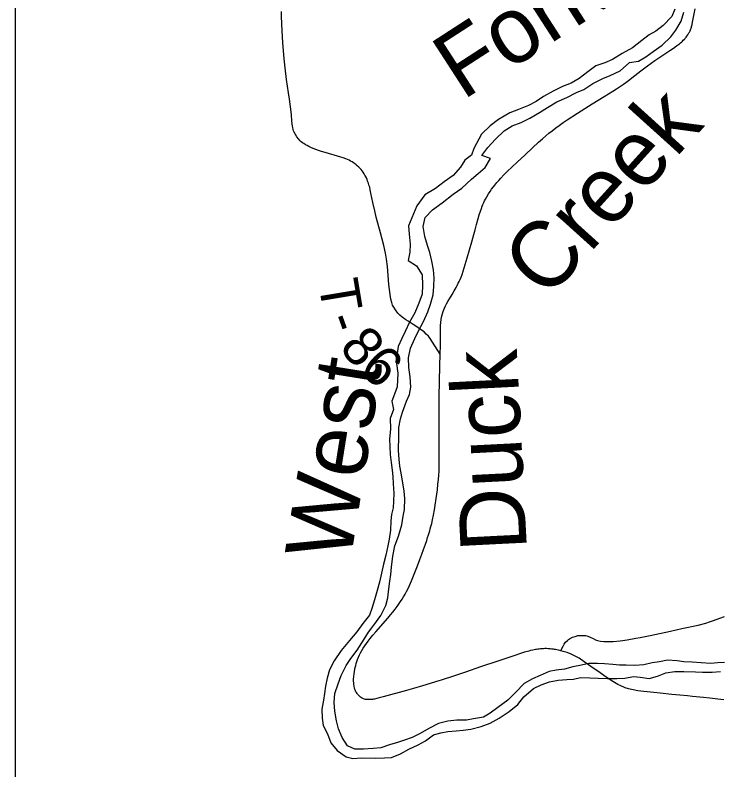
# Model space of a CAD drawing. Extents: x 0 to 34, y 0 to 22.
# Drawn here: x 2.1 to 3.105, y 14.853 to 15.933 of the extents above; entities that cross this region are included whole.
import ezdxf

# ---------------------------------------------------------------- set-up
doc = ezdxf.new("R2010")
doc.units = 0
for name, color, linetype in [('GM_X_Corporation', 7, 'Continuous'), ('GM_X_Major_River', 7, 'Continuous'), ('GM_X_Major_River_Text', 7, 'Continuous'), ('GM_X_State_Route', 7, 'Continuous'), ('GM_X_Township_Road', 7, 'Continuous'), ('GM_X_Township_Road_Text', 7, 'Continuous'), ('SH_Data', 7, 'Continuous'), ('SH_Text', 7, 'Continuous')]:
    doc.layers.add(name, color=color, linetype=linetype)

msp = doc.modelspace()

# ---------------------------------------------------------------- linework, layer by layer
at = {"layer": 'GM_X_Corporation'}
msp.add_lwpolyline([(2.1, 19.4241), (2.1, 14.1), (8.9, 14.1), (8.9, 16.8499)], dxfattribs=at)
at = {"layer": 'GM_X_Major_River'}
for points in [[(3.0436, 15.9414), (3.0392, 15.9311), (3.0268, 15.918), (3.0167, 15.9099), (3.0069, 15.9049), (2.9964, 15.8967), (2.9833, 15.8863), (2.9686, 15.8782), (2.9547, 15.8693), (2.9434, 15.8645), (2.9309, 15.8606), (2.9193, 15.8517), (2.9069, 15.8424), (2.8956, 15.8354), (2.8828, 15.8307), (2.8696, 15.8241), (2.8557, 15.8163), (2.8452, 15.8093), (2.8346, 15.8035), (2.8203, 15.798), (2.8075, 15.7933), (2.7913, 15.7836), (2.7797, 15.7747), (2.7673, 15.7628), (2.7562, 15.7421), (2.7529, 15.7326)], [(2.7677, 15.7321), (2.7763, 15.7435), (2.7871, 15.7555), (2.7995, 15.7674), (2.8111, 15.7747), (2.824, 15.7795), (2.8364, 15.7853), (2.8499, 15.7935), (2.8616, 15.8008), (2.8751, 15.809), (2.8891, 15.8153), (2.903, 15.8223), (2.9136, 15.8266), (2.9263, 15.8351), (2.9407, 15.8421), (2.9512, 15.8464), (2.9655, 15.8531), (2.979, 15.865), (2.9919, 15.8671), (3.0024, 15.8733), (3.0129, 15.881), (3.0257, 15.8899), (3.038, 15.9019), (3.0451, 15.9114), (3.0529, 15.9244), (3.0565, 15.937)], [(2.7529, 15.7326), (2.7432, 15.7253), (2.7369, 15.7153), (2.7264, 15.7034), (2.714, 15.6945), (2.7013, 15.6849), (2.6862, 15.6759), (2.6747, 15.6602), (2.6626, 15.6316), (2.6635, 15.6195), (2.6652, 15.6055), (2.6646, 15.5937), (2.6621, 15.5819), (2.6743, 15.5745), (2.6821, 15.5613), (2.683, 15.5469), (2.6825, 15.5336), (2.6773, 15.5207), (2.6718, 15.5073), (2.6641, 15.4936), (2.6582, 15.4802), (2.653, 15.4703), (2.6482, 15.4588), (2.6461, 15.4455), (2.6455, 15.4345), (2.6476, 15.4209), (2.6464, 15.4011), (2.6427, 15.3908), (2.6387, 15.3809), (2.6415, 15.3688), (2.6367, 15.3562), (2.6369, 15.3411), (2.6356, 15.3266), (2.6361, 15.316), (2.6363, 15.3043), (2.638, 15.2929), (2.6396, 15.2823), (2.6405, 15.2728), (2.641, 15.2626), (2.6416, 15.2493), (2.6414, 15.2379), (2.6407, 15.2284), (2.6382, 15.2189), (2.6376, 15.2094), (2.637, 15.1961), (2.6349, 15.1836), (2.6331, 15.1741), (2.6303, 15.1604), (2.627, 15.1475), (2.6242, 15.1349), (2.6213, 15.122), (2.6177, 15.1098), (2.6141, 15.0968), (2.6104, 15.0843), (2.6068, 15.0747), (2.5975, 15.0628), (2.5889, 15.051), (2.5785, 15.0383), (2.5665, 15.0241), (2.5565, 15.0095), (2.5498, 14.9966), (2.5462, 14.9844), (2.5441, 14.9733), (2.5427, 14.9627), (2.5413, 14.9532), (2.5388, 14.9403), (2.5394, 14.9274), (2.5407, 14.9171), (2.5469, 14.9051), (2.5516, 14.8922), (2.5605, 14.881), (2.5735, 14.8721), (2.583, 14.8699), (2.5948, 14.8708), (2.616, 14.8704), (2.6285, 14.8705), (2.6384, 14.871), (2.6515, 14.8765), (2.6632, 14.8831), (2.6764, 14.8894), (2.6869, 14.8952), (2.6986, 14.9037), (2.7091, 14.9065), (2.719, 14.9082), (2.7307, 14.9091), (2.7409, 14.9104), (2.7519, 14.9116), (2.7666, 14.9156), (2.7795, 14.9204), (2.7923, 14.9274), (2.8069, 14.9371), (2.8193, 14.9471), (2.8279, 14.9578), (2.8414, 14.9698), (2.8523, 14.9752), (2.8644, 14.9792), (2.8768, 14.9816), (2.889, 14.9829), (2.8988, 14.9834), (2.909, 14.9855), (2.9219, 14.9853)], [(2.9429, 15.0053), (2.933, 15.0055), (2.9205, 15.0054), (2.9103, 15.0033), (2.8978, 15.0009), (2.8861, 14.9977), (2.874, 14.996), (2.8638, 14.994), (2.8513, 14.9885), (2.84, 14.9838), (2.8284, 14.9768), (2.8157, 14.9641), (2.8048, 14.9533), (2.7905, 14.9425), (2.7797, 14.9344), (2.7699, 14.9286), (2.7559, 14.9265), (2.7457, 14.9245), (2.732, 14.9247), (2.7188, 14.923), (2.7056, 14.9197), (2.692, 14.9127), (2.6796, 14.9057), (2.6679, 14.8999), (2.657, 14.8959), (2.6468, 14.8928), (2.6358, 14.8892), (2.623, 14.8852), (2.612, 14.884), (2.5984, 14.883), (2.5859, 14.8832), (2.5756, 14.888), (2.5678, 14.8997), (2.5627, 14.9121), (2.5599, 14.9235), (2.5575, 14.9375), (2.5562, 14.9496), (2.5575, 14.9625), (2.5619, 14.9766), (2.5662, 14.9884), (2.5736, 15.0026), (2.5803, 15.0125), (2.5893, 15.0248), (2.5993, 15.0405), (2.6056, 15.0504), (2.613, 15.0604), (2.6231, 15.0742), (2.6305, 15.0887), (2.633, 15.0997), (2.6347, 15.1123), (2.6361, 15.1233), (2.6375, 15.1328), (2.6385, 15.1434), (2.6405, 15.159), (2.6434, 15.1739), (2.6485, 15.1876), (2.6532, 15.204), (2.6553, 15.2161), (2.6571, 15.226), (2.6576, 15.2416), (2.6567, 15.2522), (2.6547, 15.2639), (2.6522, 15.2779), (2.6505, 15.2878), (2.6493, 15.298), (2.6483, 15.3101), (2.6488, 15.3306), (2.649, 15.3431), (2.6511, 15.3553), (2.654, 15.3648), (2.6599, 15.3808), (2.6643, 15.3904), (2.6661, 15.401), (2.6651, 15.4158), (2.663, 15.4287), (2.6628, 15.4427), (2.6657, 15.4564), (2.672, 15.4705), (2.6764, 15.4804), (2.6841, 15.4946), (2.6904, 15.5087), (2.6944, 15.5194), (2.698, 15.5327), (2.699, 15.5449), (2.6996, 15.5574), (2.6983, 15.5688), (2.6962, 15.5809), (2.6934, 15.5933), (2.6899, 15.6035), (2.6859, 15.6164), (2.6838, 15.6308), (2.6867, 15.6433), (2.6971, 15.6545), (2.711, 15.6645), (2.7264, 15.6769), (2.7392, 15.6854), (2.7527, 15.6981), (2.7624, 15.7062), (2.7725, 15.715), (2.7799, 15.7277), (2.7677, 15.7321)], [(3.115, 15.0072), (3.1047, 15.0063), (3.0953, 15.0058), (3.0812, 15.0064), (3.0687, 15.0077), (3.0566, 15.008), (3.0471, 15.0094), (3.0334, 15.0103), (3.0217, 15.0082), (3.0115, 15.0066), (2.9994, 15.0038), (2.9865, 15.0025), (2.974, 15.0034), (2.9645, 15.0033), (2.955, 15.0043), (2.9429, 15.0053)], [(2.9219, 14.9853), (2.934, 14.9847), (2.9473, 14.9841), (2.9606, 14.9843), (2.972, 14.9848), (2.9848, 14.9869), (2.9943, 14.9859), (3.0068, 14.9841), (3.0189, 14.9873), (3.031, 14.9924), (3.0439, 14.9941), (3.0568, 14.9943), (3.0731, 14.9938), (3.0833, 14.9931), (3.097, 14.993), (3.1091, 14.9939)]]:
    msp.add_lwpolyline(points, dxfattribs=at)
at = {"layer": 'GM_X_State_Route'}
for points in [[(2.683, 14.9738), (2.67, 14.97), (2.6599, 14.9672), (2.6264, 14.958), (2.621, 14.9566), (2.6139, 14.9548), (2.6125, 14.9545), (2.6113, 14.9543), (2.61, 14.9542), (2.6078, 14.9539), (2.6057, 14.9539), (2.6036, 14.954), (2.6014, 14.9543), (2.5999, 14.9547), (2.5984, 14.9552), (2.5974, 14.9556), (2.5963, 14.9561), (2.5953, 14.9567), (2.5943, 14.9574), (2.5932, 14.9582), (2.592, 14.9593), (2.59, 14.9615), (2.5892, 14.9626), (2.5883, 14.9639), (2.5876, 14.9652), (2.587, 14.9666), (2.5863, 14.9681), (2.5857, 14.97), (2.5849, 14.9735), (2.5846, 14.9756), (2.5844, 14.9777), (2.5843, 14.9803), (2.5843, 14.9832), (2.5845, 14.987), (2.5849, 14.9906), (2.5853, 14.9939), (2.5859, 14.9973), (2.5865, 15), (2.5872, 15.0027), (2.588, 15.0056), (2.5889, 15.0085), (2.59, 15.0114), (2.5914, 15.0148), (2.5927, 15.0178), (2.5943, 15.0209), (2.5959, 15.024), (2.598, 15.0273), (2.6002, 15.0307), (2.6025, 15.034), (2.6051, 15.0377), (2.608, 15.0414), (2.6117, 15.0461), (2.6159, 15.051), (2.633, 15.0706), (2.6369, 15.0752), (2.6403, 15.0792), (2.6436, 15.0833), (2.6464, 15.0871), (2.6514, 15.0942), (2.6536, 15.0976), (2.6558, 15.1011), (2.658, 15.1049), (2.6601, 15.1087), (2.6623, 15.1129), (2.6643, 15.1171), (2.6658, 15.1206), (2.6672, 15.124), (2.6754, 15.1455), (2.6788, 15.1541), (2.6817, 15.1618), (2.6842, 15.1687), (2.6871, 15.1764), (2.6888, 15.1814), (2.6901, 15.1856), (2.6914, 15.1894), (2.6924, 15.1926), (2.6932, 15.1953), (2.6939, 15.1981), (2.6947, 15.2013), (2.6959, 15.2059), (2.697, 15.2109), (2.6984, 15.2177), (2.6998, 15.2254), (2.7008, 15.2318), (2.7023, 15.2415), (2.704, 15.2539), (2.7049, 15.2621), (2.7056, 15.2686), (2.7061, 15.2747), (2.7064, 15.2808), (2.7067, 15.2875), (2.7067, 15.2938), (2.7066, 15.2993), (2.7066, 15.3099), (2.7067, 15.3255), (2.7067, 15.3359), (2.7068, 15.3632), (2.7068, 15.3869), (2.7078, 15.4311), (2.7081, 15.4482), (2.7083, 15.4606), (2.7083, 15.4792), (2.7084, 15.4844), (2.7087, 15.489), (2.709, 15.4934), (2.7096, 15.4976), (2.7101, 15.5009), (2.711, 15.5042), (2.7119, 15.5074), (2.713, 15.5106), (2.7141, 15.5137), (2.7155, 15.5169), (2.7172, 15.5201), (2.719, 15.5234), (2.725, 15.5335), (2.7281, 15.5387), (2.7308, 15.5432), (2.7323, 15.5461), (2.734, 15.5493), (2.7352, 15.552), (2.7366, 15.5549), (2.738, 15.5583), (2.7394, 15.5619), (2.7426, 15.5714), (2.7469, 15.5857), (2.7531, 15.6085), (2.7561, 15.6191), (2.758, 15.6257), (2.76, 15.6334), (2.7625, 15.6419), (2.764, 15.6472), (2.7656, 15.6523), (2.767, 15.6562), (2.7683, 15.6596), (2.7693, 15.6621), (2.7704, 15.6647), (2.7716, 15.6671), (2.773, 15.6697), (2.7749, 15.673), (2.7772, 15.6771), (2.7796, 15.6808), (2.7817, 15.684), (2.7841, 15.6873), (2.7863, 15.6899), (2.7891, 15.6933), (2.7919, 15.6965), (2.7949, 15.6999), (2.7991, 15.7044), (2.8041, 15.7091), (2.8109, 15.7157), (2.818, 15.7224), (2.8294, 15.733), (2.84, 15.7432), (2.8489, 15.7512), (2.8542, 15.756), (2.8592, 15.7602), (2.8637, 15.764), (2.8683, 15.7676), (2.8733, 15.7716), (2.8781, 15.7751), (2.8839, 15.7794), (2.8898, 15.7833), (2.9043, 15.7929), (2.9254, 15.806), (2.9428, 15.8166), (2.955, 15.824), (2.9602, 15.8274), (2.9648, 15.8304), (2.9701, 15.834), (2.9738, 15.8367), (2.9776, 15.8394), (2.9866, 15.8465), (2.9951, 15.8534), (3.0045, 15.8604), (3.0151, 15.868), (3.0253, 15.8748), (3.0368, 15.8824), (3.0417, 15.8857), (3.0462, 15.8888), (3.0475, 15.8897), (3.0489, 15.8907), (3.0503, 15.8919), (3.052, 15.8932), (3.0536, 15.8948), (3.0547, 15.8958), (3.0557, 15.8969), (3.0574, 15.8986), (3.0583, 15.8996), (3.0591, 15.9006), (3.0599, 15.9016), (3.0607, 15.9027), (3.0621, 15.9047), (3.0627, 15.9057), (3.0633, 15.9067), (3.0639, 15.9077), (3.0645, 15.9086), (3.065, 15.9096), (3.0655, 15.9106), (3.066, 15.9118), (3.0665, 15.9131), (3.067, 15.9144), (3.0674, 15.9156), (3.0677, 15.9166), (3.0681, 15.9179), (3.0685, 15.9195), (3.0692, 15.923), (3.0729, 15.9418)], [(2.9727, 14.9709), (2.9717, 14.9713), (2.9666, 14.9734), (2.9622, 14.9756), (2.9548, 14.9799), (2.9455, 14.986), (2.9368, 14.992), (2.9236, 15.0013), (2.9201, 15.0039), (2.914, 15.0082), (2.9067, 15.013), (2.9012, 15.0161), (2.8955, 15.0188), (2.8897, 15.0211), (2.8841, 15.0229), (2.8807, 15.0237), (2.8771, 15.0246), (2.8751, 15.0251), (2.8732, 15.0254), (2.8715, 15.0257), (2.8701, 15.026), (2.8688, 15.0261), (2.8671, 15.0263), (2.8656, 15.0265), (2.8641, 15.0266), (2.8624, 15.0267), (2.8602, 15.0268), (2.8577, 15.0268), (2.8559, 15.0267), (2.8544, 15.0266), (2.8515, 15.0264), (2.8496, 15.0262), (2.8478, 15.026), (2.846, 15.0257), (2.8443, 15.0254), (2.8426, 15.0251), (2.8408, 15.0247), (2.8374, 15.024), (2.8351, 15.0234), (2.8329, 15.0228), (2.8308, 15.0222), (2.8288, 15.0217), (2.826, 15.0209), (2.823, 15.0199), (2.8201, 15.0191), (2.8175, 15.0181), (2.7904, 15.0089), (2.7657, 15.0006), (2.7445, 14.9934), (2.7286, 14.988), (2.7097, 14.9818), (2.7062, 14.9807), (2.683, 14.9738)], [(3.1137, 14.9534), (3.1051, 14.9548), (3.094, 14.9561), (3.0847, 14.957), (3.0692, 14.9585), (3.0618, 14.9591), (3.0507, 14.9602), (3.0396, 14.9614), (3.0229, 14.9632), (3.0136, 14.9642), (2.9994, 14.9654), (2.9908, 14.9665), (2.9841, 14.9677), (2.9776, 14.9693), (2.9727, 14.9709)]]:
    msp.add_lwpolyline(points, dxfattribs=at)
at = {"layer": 'GM_X_Township_Road'}
for points in [[(2.673, 15.4879), (2.6696, 15.4902), (2.6623, 15.495), (2.6587, 15.4973), (2.6536, 15.5009), (2.6503, 15.5037), (2.6473, 15.5068), (2.644, 15.5113), (2.6416, 15.515), (2.64, 15.5183), (2.6387, 15.5218), (2.6375, 15.5266), (2.6364, 15.5333), (2.6348, 15.5475), (2.6327, 15.5735), (2.6314, 15.584), (2.6299, 15.5926), (2.6275, 15.6035), (2.6227, 15.6215), (2.6167, 15.6437), (2.6145, 15.6528), (2.6119, 15.6649), (2.6091, 15.6783), (2.6081, 15.683), (2.6072, 15.6867), (2.6062, 15.6899), (2.6054, 15.6926), (2.6043, 15.6956), (2.6034, 15.6979), (2.6025, 15.7), (2.6014, 15.7024), (2.6005, 15.7041), (2.5992, 15.7061), (2.5979, 15.7082), (2.5964, 15.7102), (2.595, 15.7119), (2.5931, 15.7139), (2.5915, 15.7155), (2.5895, 15.7174), (2.5877, 15.7189), (2.5857, 15.7205), (2.5841, 15.7216), (2.5821, 15.7229), (2.5799, 15.7241), (2.5777, 15.7253), (2.5755, 15.7263), (2.5732, 15.7273), (2.5695, 15.7286), (2.5661, 15.7297), (2.5435, 15.7363), (2.5384, 15.7379), (2.534, 15.7393), (2.5302, 15.7407), (2.5265, 15.7422), (2.523, 15.7436), (2.5202, 15.7449), (2.5177, 15.7462), (2.5153, 15.7476), (2.5132, 15.7491), (2.5112, 15.7504), (2.5094, 15.7519), (2.5079, 15.7532), (2.5053, 15.7559), (2.503, 15.7588), (2.501, 15.7621), (2.4993, 15.7653), (2.4984, 15.7675), (2.4979, 15.7694), (2.4973, 15.772), (2.4968, 15.7742), (2.496, 15.781), (2.4952, 15.7909), (2.4926, 15.8125), (2.4912, 15.8217), (2.4882, 15.8407), (2.4862, 15.8573), (2.4849, 15.8703), (2.4829, 15.8939), (2.482, 15.9106), (2.4812, 15.9311), (2.4809, 15.9383)], [(2.7081, 15.4482), (2.6938, 15.4702), (2.6912, 15.4736), (2.6882, 15.4768), (2.685, 15.4797), (2.6799, 15.4833), (2.673, 15.4879)], [(2.9483, 15.0369), (2.9557, 15.0372), (2.9656, 15.0381), (2.9755, 15.0395), (2.9877, 15.0416), (2.9943, 15.0428), (3.0083, 15.0456), (3.0374, 15.052), (3.0538, 15.0556), (3.0769, 15.0605), (3.0881, 15.0635), (3.0934, 15.0651), (3.0974, 15.0666), (3.1149, 15.073)], [(2.8807, 15.0237), (2.8822, 15.027), (2.8838, 15.0304), (2.8854, 15.0333), (2.8875, 15.0363), (2.89, 15.0387), (2.8915, 15.0398), (2.893, 15.0408), (2.8975, 15.0431), (2.901, 15.0444), (2.9052, 15.0454), (2.9089, 15.0458), (2.912, 15.0458), (2.9157, 15.0454), (2.9193, 15.0445), (2.9228, 15.0432), (2.9267, 15.0413), (2.93, 15.0396), (2.9329, 15.0386), (2.9372, 15.0377), (2.9421, 15.0371), (2.9483, 15.0369)]]:
    msp.add_lwpolyline(points, dxfattribs=at)
at = {"layer": 'SH_Data'}
msp.add_line((2.1, 20.9), (2.1, 14.1), dxfattribs=at)
at = {"layer": 'SH_Text'}
msp.add_lwpolyline([(2.1, 16.074), (2.1, 14.1), (6.4323, 14.1)], dxfattribs=at)

# ---------------------------------------------------------------- texts
at = {"layer": 'GM_X_Major_River_Text'}
for s, height, rotation, p in [('Fork', 0.0947, 32.9054, (2.7401, 15.8102)), ('Creek', 0.09471, 47.9058, (2.8607, 15.524)), ('Duck', 0.09472, 92.8975, (2.8322, 15.1681)), ('West', 0.09472, 80.9004, (2.5793, 15.1491))]:
    msp.add_text(s, height=height, rotation=rotation, dxfattribs=at).set_placement(p)
at = {"layer": 'GM_X_Township_Road_Text'}
for s, rotation, p in [('T', 279.4799, (2.5336, 15.5506)), ('-', 289.652, (2.5434, 15.498)), ('8', 310.0312, (2.5622, 15.4571)), ('6', 317.4219, (2.5902, 15.4245))]:
    msp.add_text(s, height=0.0568, rotation=rotation, dxfattribs=at).set_placement(p)

doc.saveas('drawing.dxf')
